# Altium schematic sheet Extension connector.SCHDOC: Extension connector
size A3; DocumentNumber: MB1144; Revision: C-02; SheetNumber: 12; SheetTotal: 25; Project: STM32L476G-EVAL
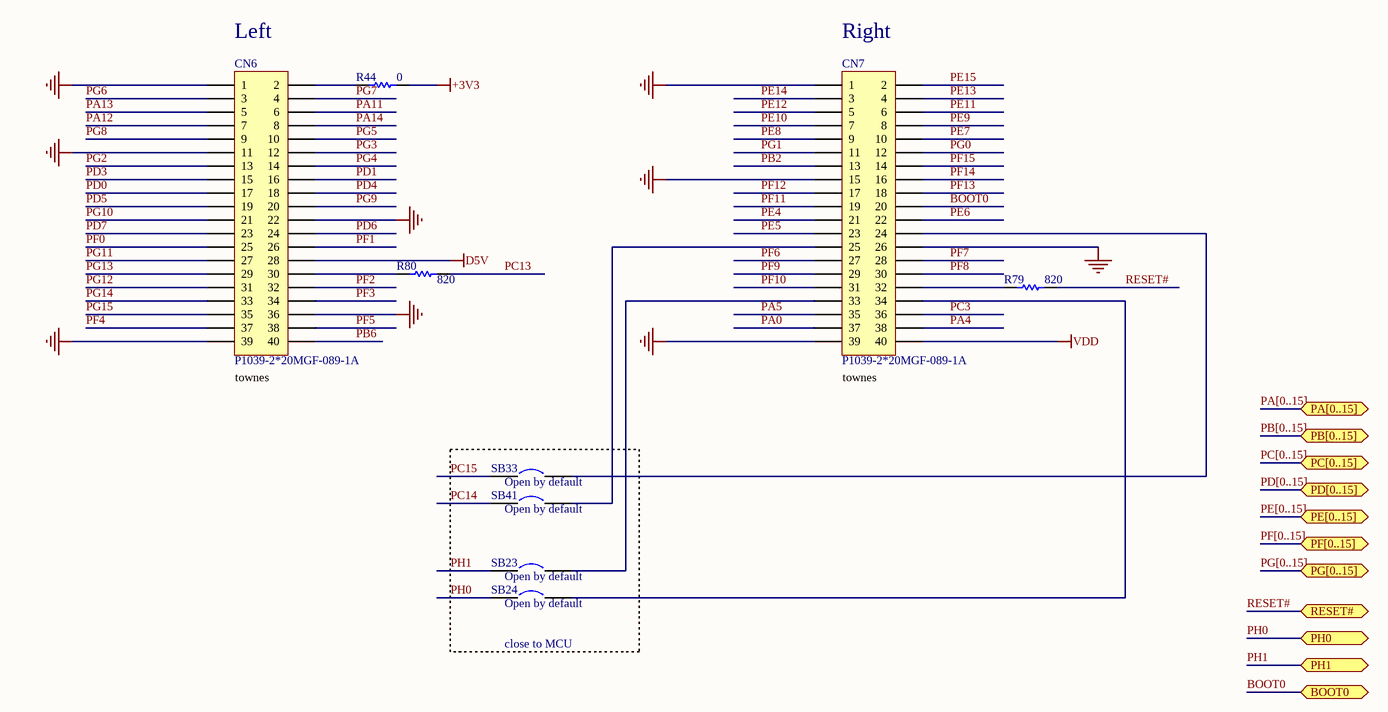
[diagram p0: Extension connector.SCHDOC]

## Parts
CN6  P1039-2*20MGF-089-1A  [FTR-120-53-L-D-LC]
CN7  P1039-2*20MGF-089-1A  [FTR-120-53-L-D-LC]
R44  0  [0603R]
R79  820  [0402R]
R80  820  [0402R]
SB23  Open by default  [SB_0603]
SB24  Open by default  [SB_0603]
SB33  Open by default  [SB_0603]
SB41  Open by default  [SB_0603]

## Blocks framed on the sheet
close to MCU: SB23 SB24 SB33 SB41

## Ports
BOOT0, PA[0..15] (bidir), PB[0..15] (bidir), PC[0..15] (bidir), PD[0..15] (bidir), PE[0..15] (bidir), PF[0..15] (bidir), PG[0..15] (bidir), PH0, PH1, RESET# (bidir)

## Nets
+3V3: R44.1
D5V: CN6.28
GND: CN6.1 CN6.11 CN6.22 CN6.36 CN6.39 CN7.1 CN7.15 CN7.26 CN7.39
VDD: CN7.40
BOOT0: CN7.20 ; port BOOT0
PA0: CN7.37
PA4: CN7.38
PA5: CN7.35
PA11: CN6.6
PA12: CN6.7
PA13: CN6.5
PA14: CN6.8
PB2: CN7.13
PB6: CN6.40
PC3: CN7.36
PC13: R80.2
PC14: SB41.1
PC15: SB33.1
PD0: CN6.17
PD1: CN6.16
PD3: CN6.15
PD4: CN6.18
PD5: CN6.19
PD6: CN6.24
PD7: CN6.23
PE4: CN7.21
PE5: CN7.23
PE6: CN7.22
PE7: CN7.10
PE8: CN7.9
PE9: CN7.8
PE10: CN7.7
PE11: CN7.6
PE12: CN7.5
PE13: CN7.4
PE14: CN7.3
PE15: CN7.2
PF0: CN6.25
PF1: CN6.26
PF2: CN6.32
PF3: CN6.34
PF4: CN6.37
PF5: CN6.38
PF6: CN7.27
PF7: CN7.28
PF8: CN7.30
PF9: CN7.29
PF10: CN7.31
PF11: CN7.19
PF12: CN7.17
PF13: CN7.18
PF14: CN7.16
PF15: CN7.14
PG0: CN7.12
PG1: CN7.11
PG2: CN6.13
PG3: CN6.12
PG4: CN6.14
PG5: CN6.10
PG6: CN6.3
PG7: CN6.4
PG8: CN6.9
PG9: CN6.20
PG10: CN6.21
PG11: CN6.27
PG12: CN6.31
PG13: CN6.29
PG14: CN6.33
PG15: CN6.35
PH0: SB24.1 ; port PH0
PH1: SB23.1 ; port PH1
RESET#: R79.1 ; port RESET#
NetCN6_2: CN6.2 R44.2
NetCN6_30: CN6.30 R80.1
NetCN7_24: CN7.24 SB33.2
NetCN7_25: CN7.25 SB41.2
NetCN7_32: CN7.32 R79.2
NetCN7_33: CN7.33 SB23.2
NetCN7_34: CN7.34 SB24.2

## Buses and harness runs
bus PA[0..15] = port PA[0..15]
bus PB[0..15] = port PB[0..15]
bus PC[0..15] = port PC[0..15]
bus PD[0..15] = port PD[0..15]
bus PE[0..15] = port PE[0..15]
bus PF[0..15] = port PF[0..15]
bus PG[0..15] = port PG[0..15]

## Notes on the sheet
- (near CN6) Left
- (near CN7) Right
- (near CN6) townes
- (near CN7) townes

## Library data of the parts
CN6 CN7 = FTR-120-53-L-D-LC: Header, 20-Pin, Dual row; Ordered by: Subcon; Comments: extension connector; ECCN_US/EU: NA
R44 R79 R80 = Res1: Resistor; Value: 1K; Ordered by: Subcon; ECCN_US/EU: NA
SB23 SB24 SB33 SB41 = Circuit Breaker: Ordered by: Subcon; Comments: Solder bridge; Fitted: NO; ECCN_US/EU: NA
